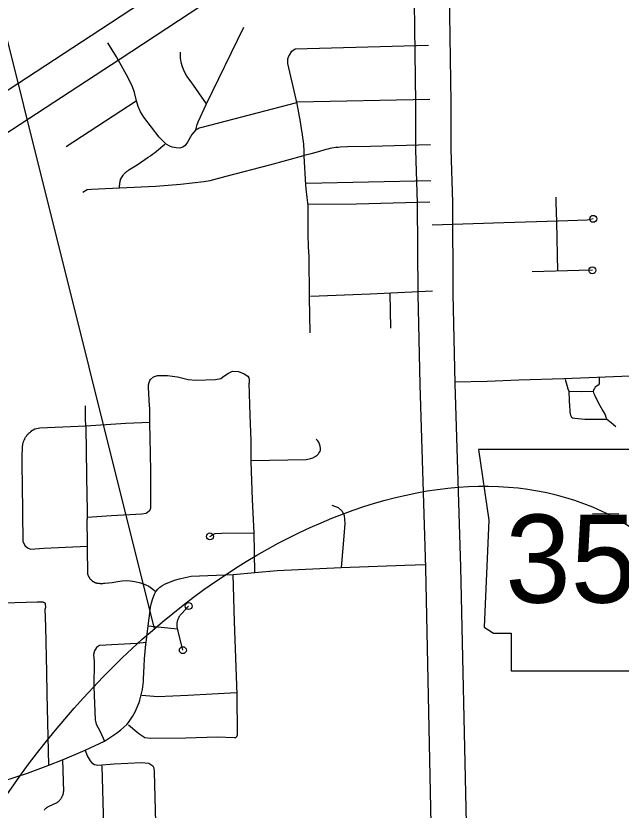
# Model space of a CAD drawing. Extents: x 309348 to 309445, y 336383 to 336484.
# Drawn here: x 309351.516 to 309352.387, y 336400.194 to 336401.336 of the extents above; entities that cross this region are included whole.
import ezdxf

# ---------------------------------------------------------------- set-up
doc = ezdxf.new("R2010")
doc.units = 0
doc.layers.add('R_Annotation', color=7, linetype='Continuous')

msp = doc.modelspace()

# ---------------------------------------------------------------- linework, layer by layer
at = {"layer": 'R_Annotation'}
for points in [[(309351.7151, 336400.4543), (309351.2446, 336402.3368), (309349.4843, 336402.3368)], [(309353.5386, 336401.9502), (309353.1512, 336401.9259), (309352.6374, 336401.8975), (309352.6056, 336401.8933), (309352.5814, 336401.8881), (309352.5234, 336401.871), (309352.4797, 336401.8556), (309352.4295, 336401.8304), (309352.3881, 336401.8076), (309352.305, 336401.7552), (309352.2745, 336401.7342), (309351.6382, 336401.3162), (309351.2388, 336401.0557)], [(309351.2388, 336401.0557), (309351.1901, 336400.9626), (309351.2211, 336400.9844), (309351.6656, 336401.2744), (309352.3024, 336401.6927), (309352.3325, 336401.7134), (309352.4136, 336401.7645), (309352.4527, 336401.7861), (309352.4993, 336401.8094), (309352.5388, 336401.8234), (309352.5938, 336401.8396), (309352.6141, 336401.844), (309352.642, 336401.8477), (309353.1541, 336401.876), (309353.5417, 336401.9003)], [(309351.7894, 336401.2084), (309351.8437, 336401.32)], [(309351.7748, 336401.1723), (309351.7691, 336401.1654), (309351.7629, 336401.1543), (309351.7593, 336401.1498), (309351.7559, 336401.147), (309351.7514, 336401.1458), (309351.7465, 336401.146), (309351.7407, 336401.1472), (309351.7373, 336401.1485), (309351.7322, 336401.1517), (309351.7218, 336401.1617), (309351.6998, 336401.1901), (309351.6952, 336401.1982), (309351.6918, 336401.2056), (309351.6894, 336401.2137), (309351.6866, 336401.2256), (309351.6832, 336401.2352), (309351.6751, 336401.251), (309351.6607, 336401.277), (309351.648, 336401.2971)], [(309351.9206, 336401.2097), (309351.9177, 336401.2222), (309351.9072, 336401.2673), (309351.9071, 336401.2678), (309351.907, 336401.2684), (309351.9069, 336401.269), (309351.9068, 336401.2695), (309351.9068, 336401.2701), (309351.9068, 336401.2706), (309351.9068, 336401.2712), (309351.9068, 336401.2718), (309351.9069, 336401.2723), (309351.9069, 336401.2729), (309351.907, 336401.2735), (309351.9071, 336401.274), (309351.9072, 336401.2746), (309351.9074, 336401.2751), (309351.9075, 336401.2757), (309351.9077, 336401.2762), (309351.9079, 336401.2767), (309351.9081, 336401.2773), (309351.9083, 336401.2778), (309351.9086, 336401.2783), (309351.9088, 336401.2788), (309351.9091, 336401.2793), (309351.9094, 336401.2797), (309351.9127, 336401.2854), (309351.9177, 336401.2885), (309352.1096, 336401.2937)], [(309351.7899, 336401.2093), (309351.7677, 336401.2411), (309351.7618, 336401.2492), (309351.759, 336401.2547), (309351.7571, 336401.2587), (309351.7552, 336401.264), (309351.7537, 336401.2694), (309351.7528, 336401.275), (309351.7524, 336401.2806), (309351.7525, 336401.2839)], [(309351.5883, 336401.1481), (309351.6886, 336401.2136)], [(309351.7748, 336401.1723), (309351.7761, 336401.1732), (309351.7778, 336401.174), (309351.7795, 336401.1748), (309351.7815, 336401.1755), (309351.7836, 336401.1761), (309351.9202, 336401.2115)], [(309351.7748, 336401.1723), (309351.7768, 336401.18), (309351.7783, 336401.1848), (309351.7894, 336401.2084)], [(309351.92, 336401.2124), (309352.1112, 336401.2164)], [(309351.9305, 336401.1341), (309351.9303, 336401.1423), (309351.9298, 336401.1505), (309351.9294, 336401.1556), (309351.9288, 336401.1607), (309351.9281, 336401.1658), (309351.9273, 336401.1709), (309351.925, 336401.1836), (309351.9206, 336401.2097)], [(309351.665, 336401.0885), (309351.665, 336401.0898), (309351.6649, 336401.091), (309351.665, 336401.0922), (309351.6651, 336401.0935), (309351.6652, 336401.0947), (309351.6653, 336401.0959), (309351.6656, 336401.0971), (309351.6658, 336401.0983), (309351.6661, 336401.0995), (309351.6664, 336401.1007), (309351.67, 336401.1068), (309351.6707, 336401.1076), (309351.6713, 336401.1084), (309351.672, 336401.1091), (309351.6727, 336401.1099), (309351.6735, 336401.1106), (309351.6742, 336401.1113), (309351.675, 336401.112), (309351.6758, 336401.1126), (309351.6766, 336401.1132), (309351.6775, 336401.1138), (309351.6783, 336401.1144), (309351.6901, 336401.1218), (309351.7062, 336401.1327), (309351.7092, 336401.1347), (309351.7122, 336401.1369), (309351.7151, 336401.1391), (309351.7179, 336401.1414), (309351.7301, 336401.1515)], [(309351.9305, 336401.1355), (309351.9405, 336401.1379), (309351.9499, 336401.1404), (309351.9592, 336401.1433), (309351.962, 336401.1442), (309351.9648, 336401.145), (309351.9677, 336401.1456), (309351.9705, 336401.1462), (309351.9734, 336401.1467), (309351.9763, 336401.1471), (309351.9792, 336401.1474), (309351.9821, 336401.1475), (309351.9927, 336401.148), (309352.0259, 336401.1488), (309352.1125, 336401.1512)], [(309351.6123, 336401.0823), (309351.6183, 336401.0861), (309351.6244, 336401.0868), (309351.665, 336401.0885), (309351.7173, 336401.091), (309351.7525, 336401.0938), (309351.7861, 336401.0976), (309351.7955, 336401.0993), (309351.8183, 336401.1055), (309351.8809, 336401.1219), (309351.9301, 336401.1351)], [(309351.9327, 336401.0929), (309351.9305, 336401.1341)], [(309351.9361, 336401.0632), (309351.9348, 336401.0749), (309351.9334, 336401.0872), (309351.9327, 336401.0929)], [(309352.1126, 336401.0989), (309351.9334, 336401.0947)], [(309351.9368, 336401.0652), (309352.0059, 336401.0657), (309352.1113, 336401.0686)], [(309352.294, 336401.0396), (309352.2931, 336401.0675), (309352.2929, 336401.0751)], [(309351.9384, 336400.9308), (309351.9377, 336400.9902), (309351.9369, 336401.0033), (309351.9365, 336401.0223), (309351.9361, 336401.0632)], [(309352.3465, 336401.0441), (309352.3377, 336401.0424), (309352.2958, 336401.0409), (309352.2177, 336401.0385), (309352.1149, 336401.0352)], [(309352.2953, 336400.9689), (309352.294, 336401.0396)], [(309352.3451, 336400.9702), (309352.3263, 336400.9697), (309352.2584, 336400.9679)], [(309352.1153, 336400.9401), (309352.0253, 336400.936), (309351.9394, 336400.9326)], [(309352.0539, 336400.9373), (309352.0548, 336400.8868)], [(309351.9392, 336400.8803), (309351.9384, 336400.9308)], [(309351.7095, 336400.813), (309351.7138, 336400.8168), (309351.7197, 336400.8186), (309351.7339, 336400.8188), (309351.7482, 336400.8171), (309351.7637, 336400.8129), (309351.7745, 336400.8122), (309351.8028, 336400.8129), (309351.8104, 336400.8144), (309351.8148, 336400.8176), (309351.8217, 336400.822), (309351.8274, 336400.825), (309351.836, 336400.8245), (309351.8441, 336400.8213), (309351.8493, 336400.8178), (309351.851, 336400.8156), (309351.8515, 336400.8131), (309351.8516, 336400.8077)], [(309352.6492, 336400.8272), (309352.6192, 336400.8251), (309352.5209, 336400.8217), (309352.4415, 336400.8191), (309352.3995, 336400.818), (309352.304, 336400.814), (309352.2394, 336400.812), (309352.1937, 336400.8103), (309352.1472, 336400.8091)], [(309351.7087, 336400.7494), (309351.7083, 336400.7705), (309351.7077, 336400.783), (309351.7069, 336400.794), (309351.7065, 336400.8011), (309351.7065, 336400.8024), (309351.7067, 336400.8053), (309351.7074, 336400.8085), (309351.7086, 336400.8115), (309351.7095, 336400.813)], [(309351.8543, 336400.6949), (309351.8542, 336400.7251), (309351.8528, 336400.7618), (309351.8516, 336400.8077)], [(309352.3062, 336400.8134), (309352.31, 336400.7998), (309352.3111, 336400.7961), (309352.312, 336400.7828), (309352.3124, 336400.7746), (309352.3127, 336400.769), (309352.3128, 336400.7661), (309352.3131, 336400.7638), (309352.3138, 336400.7616), (309352.3151, 336400.759), (309352.3166, 336400.7581), (309352.3198, 336400.7574), (309352.3345, 336400.7558), (309352.366, 336400.7562)], [(309352.3548, 336400.8157), (309352.3549, 336400.8112), (309352.3549, 336400.8087), (309352.3549, 336400.8069), (309352.3537, 336400.8047), (309352.3521, 336400.804), (309352.3494, 336400.8022), (309352.348, 336400.8003), (309352.3468, 336400.7983), (309352.3462, 336400.796), (309352.3469, 336400.7939), (309352.3489, 336400.7898), (309352.3518, 336400.7838), (309352.356, 336400.7755), (309352.3603, 336400.768), (309352.3637, 336400.7622), (309352.3646, 336400.7588), (309352.366, 336400.7562)], [(309352.3458, 336400.7958), (309352.3288, 336400.7954), (309352.3113, 336400.796)], [(309351.6162, 336400.7453), (309351.616, 336400.7577), (309351.6158, 336400.7752)], [(309351.7087, 336400.7514), (309351.6739, 336400.7497), (309351.6166, 336400.746), (309351.5502, 336400.743), (309351.5431, 336400.7418), (309351.5374, 336400.7381)], [(309351.7082, 336400.6241), (309351.7084, 336400.6245), (309351.7086, 336400.6249), (309351.7088, 336400.6253), (309351.709, 336400.6257), (309351.7091, 336400.6261), (309351.7093, 336400.6265), (309351.7094, 336400.627), (309351.7095, 336400.6274), (309351.7097, 336400.6278), (309351.7098, 336400.6283), (309351.7098, 336400.6287), (309351.7099, 336400.6292), (309351.7099, 336400.6296), (309351.71, 336400.63), (309351.71, 336400.6305), (309351.71, 336400.6309), (309351.7099, 336400.6817), (309351.709, 336400.7297), (309351.7087, 336400.7494)], [(309352.366, 336400.7562), (309352.3723, 336400.7513), (309352.3787, 336400.7453)], [(309351.5262, 336400.5797), (309351.5253, 336400.663), (309351.5249, 336400.6881), (309351.5249, 336400.7019), (309351.5253, 336400.7158), (309351.5254, 336400.7168), (309351.5255, 336400.7178), (309351.5256, 336400.7188), (309351.5258, 336400.7198), (309351.526, 336400.7208), (309351.5262, 336400.7218), (309351.5265, 336400.7227), (309351.5268, 336400.7237), (309351.5271, 336400.7246), (309351.5275, 336400.7256), (309351.5279, 336400.7265), (309351.5284, 336400.7274), (309351.5288, 336400.7283), (309351.5293, 336400.7292), (309351.5298, 336400.7301), (309351.5304, 336400.7309), (309351.531, 336400.7317), (309351.5316, 336400.7325), (309351.5322, 336400.7333), (309351.5329, 336400.7341), (309351.5336, 336400.7348), (309351.5343, 336400.7355), (309351.535, 336400.7362), (309351.5358, 336400.7368), (309351.5366, 336400.7375), (309351.5374, 336400.7381), (309351.5382, 336400.7386)], [(309351.6162, 336400.7453), (309351.6163, 336400.7411), (309351.6168, 336400.714), (309351.6175, 336400.672), (309351.6184, 336400.6246), (309351.6185, 336400.6124)], [(309351.8543, 336400.6966), (309351.9332, 336400.6982), (309351.9359, 336400.6984), (309351.9395, 336400.6992), (309351.943, 336400.7005), (309351.9463, 336400.7022), (309351.9492, 336400.7044), (309351.9511, 336400.7062), (309351.9518, 336400.7071), (309351.9531, 336400.7091), (309351.9538, 336400.7114), (309351.954, 336400.7139), (309351.954, 336400.7139), (309351.9537, 336400.717), (309351.9528, 336400.72), (309351.9514, 336400.7228), (309351.9496, 336400.7254), (309351.9493, 336400.7257), (309351.9477, 336400.7273)], [(309351.8585, 336400.5927), (309351.856, 336400.6399), (309351.8543, 336400.6949)], [(309351.7082, 336400.6241), (309351.7032, 336400.6203), (309351.6968, 336400.6193), (309351.6532, 336400.6168), (309351.6183, 336400.6144)], [(309351.9705, 336400.6321), (309351.9796, 336400.6291), (309351.9853, 336400.6237), (309351.988, 336400.6173), (309351.989, 336400.6058), (309351.9875, 336400.5878), (309351.9838, 336400.5428)], [(309351.6189, 336400.5716), (309351.6188, 336400.5763), (309351.6185, 336400.6124)], [(309352.3833, 336400.62), (309352.3455, 336400.6193)], [(309351.7949, 336400.5873), (309351.8025, 336400.5915), (309351.8119, 336400.592), (309351.8585, 336400.5927)], [(309351.8597, 336400.5356), (309351.8585, 336400.5927)], [(309351.5262, 336400.5797), (309351.5285, 336400.5743), (309351.5325, 336400.5711), (309351.5369, 336400.5691), (309351.5558, 336400.5703), (309351.6082, 336400.5728), (309351.6183, 336400.5733)], [(309351.6193, 336400.5324), (309351.6189, 336400.5716)], [(309351.8597, 336400.5356), (309351.8916, 336400.5383), (309351.9838, 336400.5428), (309352.0751, 336400.5462), (309352.1052, 336400.547)], [(309351.6193, 336400.5324), (309351.6195, 336400.5319), (309351.6197, 336400.5313), (309351.6199, 336400.5307), (309351.6201, 336400.5302), (309351.6204, 336400.5296), (309351.6207, 336400.5291), (309351.621, 336400.5286), (309351.6213, 336400.5281), (309351.6216, 336400.5276), (309351.6219, 336400.5271), (309351.6223, 336400.5266), (309351.6227, 336400.5261), (309351.6231, 336400.5257), (309351.6235, 336400.5252), (309351.6239, 336400.5248), (309351.6243, 336400.5244), (309351.6248, 336400.524), (309351.6253, 336400.5236), (309351.6257, 336400.5232), (309351.6262, 336400.5229), (309351.6267, 336400.5226), (309351.6272, 336400.5223), (309351.6278, 336400.522), (309351.6283, 336400.5217), (309351.6288, 336400.5214), (309351.6294, 336400.5212), (309351.6299, 336400.521), (309351.6305, 336400.5208), (309351.6311, 336400.5206), (309351.6317, 336400.5204), (309351.6322, 336400.5203), (309351.6328, 336400.5202), (309351.6334, 336400.5201), (309351.634, 336400.52), (309351.6354, 336400.5199), (309351.6367, 336400.5198), (309351.6381, 336400.5197), (309351.6394, 336400.5197), (309351.6408, 336400.5198), (309351.6421, 336400.5199), (309351.6435, 336400.52), (309351.6489, 336400.5205), (309351.6543, 336400.5209), (309351.6619, 336400.5223), (309351.6688, 336400.5235), (309351.6744, 336400.524), (309351.6801, 336400.5233), (309351.687, 336400.5226), (309351.6949, 336400.5204), (309351.7027, 336400.5178), (309351.7071, 336400.5156), (309351.711, 336400.513), (309351.7173, 336400.5082)], [(309351.7173, 336400.5082), (309351.7202, 336400.5116), (309351.7227, 336400.5142), (309351.7256, 336400.5165), (309351.7289, 336400.5184), (309351.7297, 336400.5188), (309351.7382, 336400.5222), (309351.7439, 336400.5243), (309351.7511, 336400.5265), (309351.7593, 336400.5285), (309351.7677, 336400.53), (309351.7681, 336400.5301), (309351.8282, 336400.5328)], [(309351.8282, 336400.5328), (309351.8597, 336400.5356)], [(309351.8305, 336400.4652), (309351.8282, 336400.5328)], [(309351.706, 336400.4588), (309351.7088, 336400.4808), (309351.7095, 336400.4855), (309351.711, 336400.4919), (309351.7129, 336400.4982), (309351.7154, 336400.5043), (309351.7173, 336400.5082)], [(309351.4983, 336400.4919), (309351.5462, 336400.4931), (309351.5543, 336400.4932), (309351.5545, 336400.4932), (309351.5547, 336400.4931), (309351.5549, 336400.4931), (309351.5551, 336400.493), (309351.5553, 336400.4929), (309351.5555, 336400.4928), (309351.5557, 336400.4927), (309351.5559, 336400.4926), (309351.5561, 336400.4925), (309351.5563, 336400.4924), (309351.5565, 336400.4923), (309351.5567, 336400.4922), (309351.5569, 336400.492), (309351.5571, 336400.4919), (309351.5572, 336400.4917), (309351.5574, 336400.4916), (309351.5576, 336400.4914), (309351.5577, 336400.4913), (309351.5579, 336400.4911), (309351.558, 336400.4909), (309351.5581, 336400.4908), (309351.5582, 336400.4846)], [(309351.7483, 336400.4543), (309351.7482, 336400.4548), (309351.7481, 336400.4556), (309351.7479, 336400.4564), (309351.7478, 336400.4572), (309351.7477, 336400.458), (309351.7477, 336400.4588), (309351.7477, 336400.4596), (309351.7477, 336400.4604), (309351.7477, 336400.4612), (309351.7477, 336400.462), (309351.7478, 336400.4628), (309351.7479, 336400.4636), (309351.7481, 336400.4644), (309351.7482, 336400.4652), (309351.7484, 336400.466), (309351.7487, 336400.4668), (309351.7489, 336400.4676), (309351.7492, 336400.4683), (309351.7495, 336400.4691), (309351.7498, 336400.4698), (309351.7501, 336400.4705), (309351.7505, 336400.4713), (309351.7509, 336400.472), (309351.7513, 336400.4727), (309351.7518, 336400.4733), (309351.7522, 336400.474), (309351.7527, 336400.4747), (309351.7532, 336400.4753), (309351.7538, 336400.4759), (309351.7543, 336400.4765), (309351.7643, 336400.4872)], [(309351.5601, 336400.3922), (309351.5587, 336400.4575), (309351.5581, 336400.4834), (309351.5582, 336400.4836), (309351.5582, 336400.4838), (309351.5582, 336400.484), (309351.5582, 336400.4842), (309351.5582, 336400.4845), (309351.5582, 336400.4846)], [(309351.8341, 336400.3599), (309351.8305, 336400.4652)], [(309351.7028, 336400.4326), (309351.703, 336400.4348), (309351.706, 336400.4588)], [(309351.706, 336400.4588), (309351.7483, 336400.4543)], [(309351.756, 336400.4238), (309351.749, 336400.4512), (309351.7483, 336400.4543)], [(309351.703, 336400.4348), (309351.69, 336400.4332), (309351.6363, 336400.4306), (309351.6319, 336400.4278), (309351.6287, 336400.423), (309351.6274, 336400.4176), (309351.6284, 336400.4077), (309351.628, 336400.3709), (309351.6299, 336400.3238), (309351.6315, 336400.3172), (309351.6369, 336400.3067), (309351.6433, 336400.293)], [(309351.6952, 336400.3557), (309351.6962, 336400.3594), (309351.6971, 336400.3632), (309351.6978, 336400.3671), (309351.6984, 336400.3709), (309351.6989, 336400.3748), (309351.6992, 336400.3787), (309351.6994, 336400.3826), (309351.7002, 336400.4008), (309351.7008, 336400.4114), (309351.7016, 336400.422), (309351.7028, 336400.4326)], [(309351.5631, 336400.2583), (309351.5607, 336400.3608), (309351.5601, 336400.3922)], [(309351.833, 336400.3626), (309351.7631, 336400.3585), (309351.7202, 336400.3566), (309351.697, 336400.3588)], [(309351.8298, 336400.2984), (309351.8324, 336400.2984), (309351.8326, 336400.2986), (309351.8327, 336400.2987), (309351.8329, 336400.2988), (309351.833, 336400.299), (309351.8332, 336400.2991), (309351.8333, 336400.2993), (309351.8334, 336400.2994), (309351.8335, 336400.2996), (309351.8336, 336400.2997), (309351.8337, 336400.2999), (309351.8338, 336400.3001), (309351.8339, 336400.3003), (309351.834, 336400.3004), (309351.8341, 336400.3006), (309351.8342, 336400.3008), (309351.8343, 336400.301), (309351.8343, 336400.3012), (309351.8344, 336400.3014), (309351.8344, 336400.3015), (309351.8345, 336400.3017), (309351.8345, 336400.3019), (309351.8345, 336400.3021), (309351.8346, 336400.3023), (309351.8346, 336400.3025), (309351.8346, 336400.3027), (309351.8346, 336400.3029), (309351.8341, 336400.3599)], [(309351.6753, 336400.3167), (309351.6776, 336400.3196), (309351.6797, 336400.3225), (309351.6818, 336400.3255), (309351.6837, 336400.3286), (309351.6855, 336400.3318), (309351.6873, 336400.335), (309351.6889, 336400.3383), (309351.6903, 336400.3417), (309351.6917, 336400.3451), (309351.693, 336400.3485), (309351.6941, 336400.352), (309351.6952, 336400.3557)], [(309351.4972, 336400.2352), (309351.5327, 336400.2471), (309351.5631, 336400.2583), (309351.5827, 336400.2659), (309351.6156, 336400.2798), (309351.6433, 336400.293), (309351.6605, 336400.3043), (309351.6668, 336400.3094), (309351.6753, 336400.3167)], [(309351.6776, 336400.3165), (309351.6925, 336400.3041), (309351.7014, 336400.2981), (309351.7094, 336400.2971), (309351.7602, 336400.2975), (309351.8054, 336400.299), (309351.8298, 336400.2984)], [(309351.6156, 336400.2798), (309351.6185, 336400.2719), (309351.6226, 336400.2646), (309351.6252, 336400.2617), (309351.6287, 336400.2592), (309351.6338, 336400.2585), (309351.657, 336400.2601), (309351.6964, 336400.2624), (309351.7068, 336400.2611), (309351.7126, 336400.2576), (309351.7142, 336400.2544), (309351.7145, 336400.2487), (309351.7164, 336400.1756), (309351.7173, 336400.1057), (309351.7186, 336400.0488), (309351.7186, 336400.0351)], [(309351.5827, 336400.2659), (309351.5841, 336400.2205), (309351.584, 336400.2198), (309351.5839, 336400.219), (309351.5837, 336400.2182), (309351.5836, 336400.2174), (309351.5834, 336400.2166), (309351.5831, 336400.2159), (309351.5829, 336400.2151), (309351.5826, 336400.2144), (309351.5823, 336400.2136), (309351.582, 336400.2129), (309351.5816, 336400.2122), (309351.5813, 336400.2115), (309351.5809, 336400.2108), (309351.5804, 336400.2101), (309351.58, 336400.2095), (309351.5795, 336400.2088), (309351.579, 336400.2082), (309351.5785, 336400.2076), (309351.578, 336400.207), (309351.5774, 336400.2065), (309351.5769, 336400.2059), (309351.5763, 336400.2054), (309351.5757, 336400.2049), (309351.5621, 336400.1984), (309351.5614, 336400.1979), (309351.5607, 336400.1975), (309351.56, 336400.197), (309351.5594, 336400.1965), (309351.5588, 336400.1959), (309351.5581, 336400.1954), (309351.5576, 336400.1948), (309351.557, 336400.1942), (309351.5564, 336400.1936)], [(309351.6393, 336400.2572), (309351.6419, 336400.1707)]]:
    msp.add_lwpolyline(points, dxfattribs=at)
for points in [[(309352.0852, 336401.5472), (309352.1342, 336401.5816), (309352.1376, 336401.4649), (309352.1413, 336401.2113), (309352.1414, 336401.1436), (309352.1437, 336401.068), (309352.1443, 336400.9364), (309352.1473, 336400.8071), (309352.1554, 336400.5429), (309352.1634, 336400.1751), (309352.1133, 336400.1741), (309352.1054, 336400.5416), (309352.0973, 336400.8057), (309352.0943, 336400.9357), (309352.0936, 336401.0671), (309352.0914, 336401.1428), (309352.0913, 336401.2109), (309352.0876, 336401.4638)], [(309352.1811, 336400.7124), (309352.1964, 336400.6108), (309352.1896, 336400.4568), (309352.2031, 336400.4484), (309352.2285, 336400.4484), (309352.2285, 336400.3942), (309352.4417, 336400.3942), (309352.4519, 336400.4162), (309352.4485, 336400.4518), (309352.4536, 336400.4924), (309352.4722, 336400.5245), (309352.4841, 336400.5482), (309352.501, 336400.5736), (309352.5111, 336400.6007), (309352.5196, 336400.6227), (309352.5348, 336400.6413), (309352.5382, 336400.6531), (309352.5314, 336400.6616), (309352.479, 336400.6616), (309352.4908, 336400.6853), (309352.4925, 336400.7005), (309352.4855, 336400.7122)]]:
    msp.add_lwpolyline(points, close=True, dxfattribs=at)
for centre in [(309352.3465, 336401.0441), (309352.3451, 336400.9702), (309351.7949, 336400.5873), (309351.7643, 336400.4872), (309351.756, 336400.4238)]:
    msp.add_circle(centre, 0.005, dxfattribs=at)
msp.add_ellipse((309351.9438, 336399.908), major_axis=(-0.4621, -0.6892), ratio=0.64799, dxfattribs=at)

# ---------------------------------------------------------------- texts
msp.add_text('351', height=0.12664, dxfattribs=at).set_placement((309352.2198, 336400.4921))

doc.saveas('drawing.dxf')
